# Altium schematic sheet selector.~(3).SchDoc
size A4
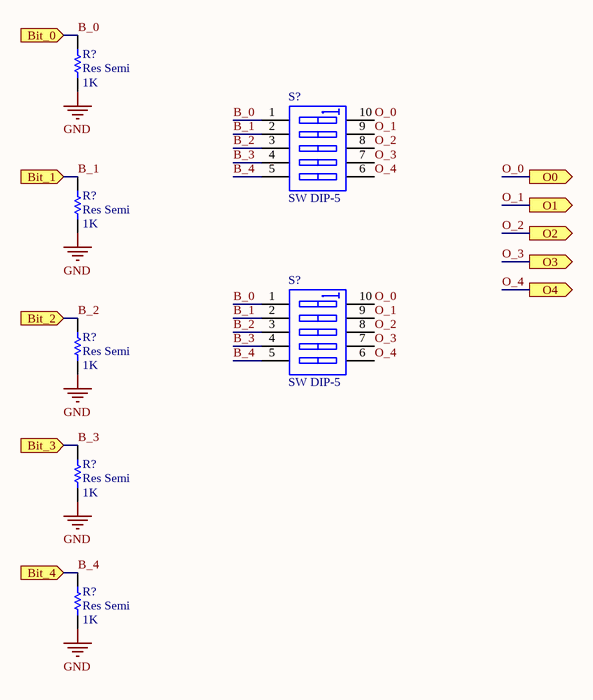
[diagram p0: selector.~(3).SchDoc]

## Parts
(Parts that share a designator on the sheet are numbered #1, #2 ... from top to bottom, then left to right.)
R?#1  Res Semi  value 1K  [2012[0805]]
R?#2  Res Semi  value 1K  [2012[0805]]
R?#3  Res Semi  value 1K  [2012[0805]]
R?#4  Res Semi  value 1K  [2012[0805]]
R?#5  Res Semi  value 1K  [2012[0805]]
S?#1  SW DIP-5  [N10A]
S?#2  SW DIP-5  [N10A]

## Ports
Bit_0 (in), Bit_1 (in), Bit_2 (in), Bit_3 (in), Bit_4 (in), O0 (out), O1 (out), O2 (out), O3 (out), O4 (out)

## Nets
GND: R?#1.1 R?#2.1 R?#3.1 R?#4.1 R?#5.1
B_0: R?#1.2 S?#1.1(A1) S?#2.1(A1) ; port Bit_0
B_1: R?#2.2 S?#1.2(A2) S?#2.2(A2) ; port Bit_1
B_2: R?#3.2 S?#1.3(A3) S?#2.3(A3) ; port Bit_2
B_3: R?#4.2 S?#1.4(A4) S?#2.4(A4) ; port Bit_3
B_4: R?#5.2 S?#1.5(A5) S?#2.5(A5) ; port Bit_4
O_0: S?#1.10(B1) S?#2.10(B1) ; port O0
O_1: S?#1.9(B2) S?#2.9(B2) ; port O1
O_2: S?#1.8(B3) S?#2.8(B3) ; port O2
O_3: S?#1.7(B4) S?#2.7(B4) ; port O3
O_4: S?#1.6(B5) S?#2.6(B5) ; port O4

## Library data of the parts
R?#1-R?#5 = Res Semi: Semiconductor Resistor
S?#1 S?#2 = SW DIP-5: DIP Switch, 5 Position, SPST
